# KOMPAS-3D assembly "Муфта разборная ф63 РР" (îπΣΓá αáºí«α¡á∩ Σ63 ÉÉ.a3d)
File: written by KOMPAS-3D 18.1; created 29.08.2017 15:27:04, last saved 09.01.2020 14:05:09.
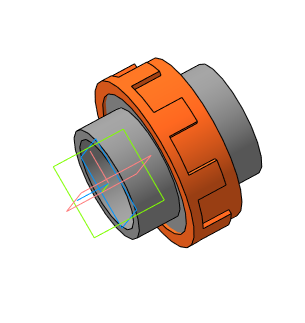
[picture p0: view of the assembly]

Document properties: Автор: Милов; Организация: Милов; Полное имя файла: D:\Magna\Магна Ins\Магна ins 32\Для Караби\Муфта разборная ф63 РР.a3d

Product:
- Part/product: Муфта разборная ф63 РР
    Масса: 1.69089
  - Body: Тело 2
      Масса: 1.00492
  - Body: Тело 1
      Масса: 0.590292
  - Component [detail]: Фланец МР ф63 РР  | pos. 5  | Материал: Полипропилен  ГОСТ 26996-86 (density 900 kg/m3); Раздел спецификации: Детали; source file: Фланец МР ф63 РР.m3d
  - Component [detail]: Фланец прижимной МР ф63 РР  | pos. 4  | Материал: Полипропилен  ГОСТ 26996-86 (density 900 kg/m3); Раздел спецификации: Детали; source file: Фланец прижимной МР ф63 РР.m3d
  - Component [detail]: Гайка МР ф63 РР  | pos. 6  | Материал: Полипропилен  ГОСТ 26996-86 (density 900 kg/m3); Масса: 0.0956773; Раздел спецификации: Детали; source file: Гайка МР ф63 РР.m3d
- Part/product: Муфта разборная ф75 РР  | designation 1
    Масса: 0.539087
  - Component [detail]: Гайка МР ф75 РР  | designation 01  | pos. 6  | Материал: Полипропилен  ГОСТ 26996-86 (density 900 kg/m3); Масса: 0.0956773; Раздел спецификации: Детали
  - Component [detail]: Фланец прижимной МР ф75 РР  | designation 01  | pos. 4  | Материал: Полипропилен  ГОСТ 26996-86 (density 900 kg/m3); Масса: 0.119147; Раздел спецификации: Детали
  - Component [detail]: Фланец МР ф75 РР  | designation 1  | pos. 5  | Материал: Полипропилен  ГОСТ 26996-86 (density 900 kg/m3); Масса: 0.139269; Раздел спецификации: Детали

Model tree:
1. Элемент выдавливания:1  (with: Операция вращения:1)
     Расстояние 2 = 12
2. Элемент выдавливания:2  (with: Операция выдавливания:1)
     Расстояние 2 = 31.5
3. Элемент выдавливания:3  (with: Элемент выдавливания:1)
     Расстояние 1 = 13
4. Элемент выдавливания:4  (with: Элемент выдавливания:2)
     Расстояние 1 = 13
5. Сечение поверхностью:1  (with: Операция вращения:1)  (labels: Полипропилен  ГОСТ 26996-86)

Referenced files in D:\Magna\Магна Ins\Магна ins 32\Для Караби\: Фланец МР ф63 РР.m3d, Фланец прижимной МР ф63 РР.m3d, Гайка МР ф63 РР.m3d
Referenced files in D:\1 ПКИ 3D\Полипропиленовые фитинги, трубы\Разборные муфты\: Фланец МР ф63 РР.m3d, Гайка МР ф63 РР.m3d, Фланец прижимной МР ф63 РР.m3d
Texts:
  (в комплекте с уплотнительным кольцом  ГОСТ 9833)
  Муфта разборная ф75 РР / (в комплекте с уплотнительным кольцом  ГОСТ 9833)

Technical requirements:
  Gost Type A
